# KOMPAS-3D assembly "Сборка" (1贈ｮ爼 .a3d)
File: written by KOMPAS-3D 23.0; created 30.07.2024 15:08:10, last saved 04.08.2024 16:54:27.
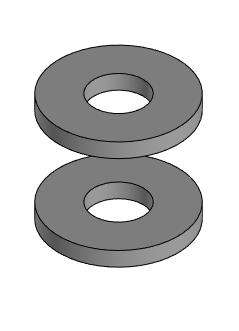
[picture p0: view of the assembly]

Document properties: Автор: zaytsev; Полное имя файла: C:\kompas install\3\KompasVar_xaml\KompasVar\model\1Сборка.a3d

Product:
- Component [detail]: Деталь  | qty 2  | Масса: 0.34355; Автор: zaytsev; source file: 1Деталь.m3d
- Part/product: Сборка
    Масса: 0.687101

Referenced files in C:\kompas install\3\KompasVar_xaml\KompasVar\model\: 1Деталь.m3d
Referenced files in C:\Users\zaytsev\Documents\: 1Деталь.m3d
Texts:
  Деталь (1)
  Деталь (2)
